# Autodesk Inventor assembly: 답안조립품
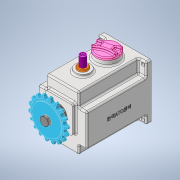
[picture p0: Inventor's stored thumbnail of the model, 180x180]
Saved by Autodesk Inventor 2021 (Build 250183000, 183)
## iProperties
Created: 2022-08
Part Number: 답안조립품
Document SubType Name: Assembly
Designer: Owner
Author: Owner
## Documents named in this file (16)
- C:\Users\Owner\Desktop\720810V1008\답안조립품.iam
- C:\Users\Owner\Desktop\720810V1008\본체.ipt
- C:\Users\Owner\Desktop\720810V1008\멈춤나사 M3.ipt
- C:\Users\Owner\Desktop\720810V1008\메인 축.ipt
- C:\Users\Owner\Desktop\720810V1008\베어링 608.ipt
- C:\Users\Owner\Desktop\720810V1008\베어링 6003.ipt
- C:\Users\Owner\Desktop\720810V1008\볼트 M4 x 10.ipt
- C:\Users\Owner\Desktop\720810V1008\부시.ipt
- C:\Users\Owner\Desktop\720810V1008\상부 캡.ipt
- C:\Users\Owner\Desktop\720810V1008\서브 축.ipt
- C:\Users\Owner\Desktop\720810V1008\스프로킷.ipt
- C:\Users\Owner\Desktop\720810V1008\슬라이더.ipt
- C:\Users\Owner\Desktop\720810V1008\오일 실 8 x 22 x 7.ipt
- C:\Users\Owner\Desktop\720810V1008\오일 실 17 x 32 x 8.ipt
- C:\Users\Owner\Desktop\720810V1008\커버.ipt
- C:\Users\Owner\Desktop\720810V1008\키 5 x 5.ipt
